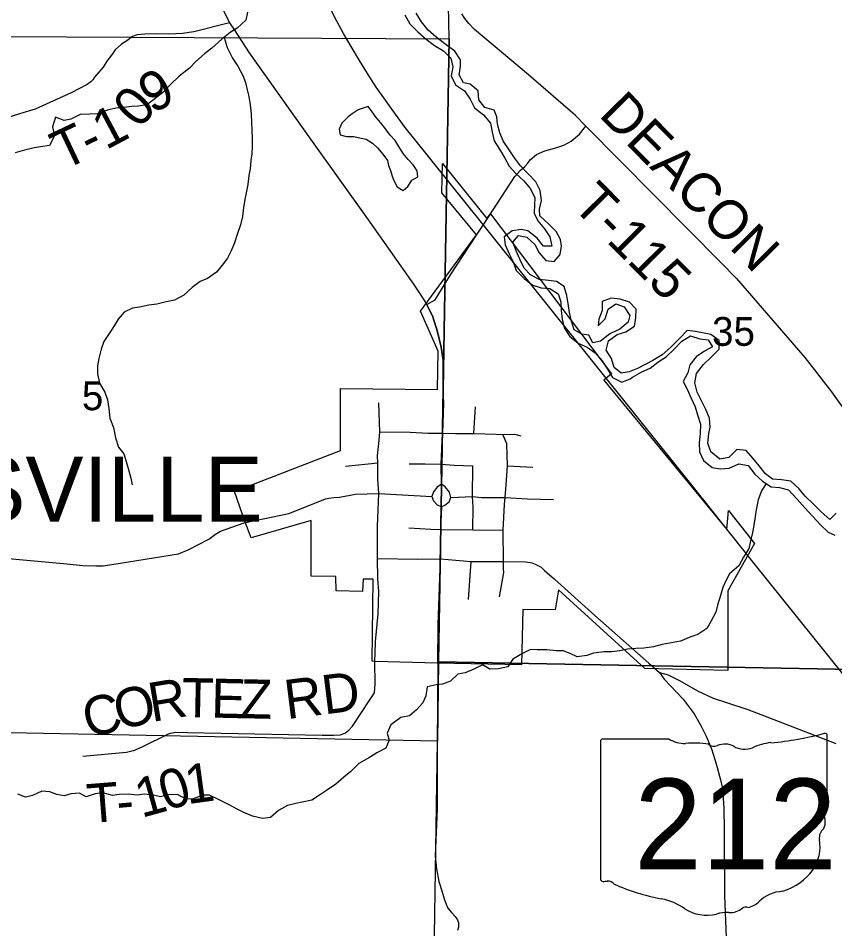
# Model space of a CAD drawing. Extents: x 0 to 34, y 0 to 22.
# Drawn here: x 3.131 to 4.318, y 18.627 to 19.951 of the extents above; entities that cross this region are included whole.
import ezdxf

# ---------------------------------------------------------------- set-up
doc = ezdxf.new("R2010")
doc.units = 0
for name, color, linetype in [('Default', 7, 'Continuous'), ('GM_X_City_Street', 7, 'Continuous'), ('GM_X_Corporation', 7, 'Continuous'), ('GM_X_County_Road', 7, 'Continuous'), ('GM_X_County_Road_Text', 7, 'Continuous'), ('GM_X_Interchange_Ramps', 7, 'Continuous'), ('GM_X_Interstate_Route', 7, 'Continuous'), ('GM_X_Major_River_Text', 7, 'Continuous'), ('GM_X_Minor_Lake', 7, 'Continuous'), ('GM_X_Minor_River', 7, 'Continuous'), ('GM_X_Section', 7, 'Continuous'), ('GM_X_Township_Road_Text', 7, 'Continuous'), ('GM_X_Township_Text', 7, 'Continuous'), ('GM_X_Unincorporated', 7, 'Continuous'), ('GM_X_Unincorporated_Text', 7, 'Continuous'), ('GM_X_US_Location', 7, 'Continuous')]:
    doc.layers.add(name, color=color, linetype=linetype)

msp = doc.modelspace()

# ---------------------------------------------------------------- linework, layer by layer
at = {"layer": 'Default'}
msp.add_lwpolyline([(3.7753, 20.9), (2.759, 20.9), (2.7373, 19.9264), (3.7574, 19.9211), (3.7556, 20.0185)], close=True, dxfattribs=at)
at = {"layer": 'GM_X_City_Street'}
msp.add_lwpolyline([(3.4457, 19.2626), (3.5997, 19.3223), (3.5997, 19.4123), (3.7404, 19.411), (3.7417, 19.467), (3.7161, 19.5247), (3.7972, 19.636), (3.747, 19.697), (3.748, 19.7395), (3.8125, 19.6595), (3.8178, 19.6664), (3.9934, 19.434), (3.9825, 19.4244), (4.1614, 19.2072), (4.1637, 19.2349), (4.2016, 19.1872), (4.1629, 19.1183), (4.1626, 19.0024), (4.0419, 19.0051), (3.9164, 19.1198), (3.9117, 19.0905), (3.8647, 19.0913), (3.8625, 19.0106), (3.7408, 19.0131), (3.6494, 19.0157), (3.6454, 19.0158), (3.6472, 19.1353), (3.6324, 19.1354), (3.6314, 19.1173), (3.5932, 19.1183), (3.5929, 19.1393), (3.557, 19.1395), (3.5569, 19.2207), (3.4695, 19.1951), (3.4612, 19.2182)], close=True, dxfattribs=at)
at = {"layer": 'GM_X_Corporation'}
for p, q in [((3.7458, 19.3025), (3.7478, 19.3473)), ((3.7463, 19.2732), (3.7458, 19.3025))]:
    msp.add_line(p, q, dxfattribs=at)
for points in [[(3.8079, 19.6516), (3.8532, 19.7209), (3.861, 19.7293), (3.8678, 19.7354), (3.8718, 19.7402), (3.8754, 19.7452), (3.8846, 19.7528), (3.8967, 19.7579), (3.9125, 19.7624), (3.9243, 19.7665), (3.9351, 19.7722), (3.9471, 19.7824), (3.9561, 19.7938), (3.9411, 19.8095), (3.8727, 19.8687), (3.7945, 19.9343), (3.786, 19.9433), (3.7801, 19.9505), (3.7759, 19.9571)], [(3.725, 19.5344), (3.7373, 19.5415), (3.7597, 19.5778), (3.7974, 19.6354), (3.8079, 19.6516)], [(3.749, 19.4004), (3.7489, 19.4537), (3.746, 19.4725), (3.7406, 19.4951), (3.734, 19.5166), (3.725, 19.5344)], [(3.7478, 19.3473), (3.7491, 19.3908), (3.749, 19.4004)], [(3.7602, 19.2542), (3.7581, 19.2615), (3.7518, 19.2694), (3.7463, 19.2732)], [(3.4595, 19.217), (3.4614, 19.2177), (3.5246, 19.2306), (3.5503, 19.2409), (3.578, 19.2521), (3.5826, 19.2532), (3.5901, 19.254), (3.5981, 19.2543), (3.6212, 19.2588), (3.6555, 19.2597), (3.7325, 19.2556)], [(3.7325, 19.2556), (3.7349, 19.2492), (3.7401, 19.2435), (3.7464, 19.2402)], [(3.7464, 19.2402), (3.7515, 19.2427), (3.7577, 19.2475), (3.7602, 19.2542)], [(2.1, 18.8956), (2.109, 18.8968), (2.1275, 18.9017), (2.1814, 18.9185), (2.2418, 18.9368), (2.293, 18.9513), (2.3675, 18.9688), (2.6484, 19.0502), (3.0219, 19.1608), (3.0376, 19.1648), (3.0493, 19.1666), (3.0647, 19.1685), (3.0897, 19.1679), (3.1971, 19.1578), (3.225, 19.1553), (3.244, 19.1548), (3.2547, 19.1546), (3.2795, 19.1586), (3.364, 19.1721), (3.3779, 19.1781), (3.4083, 19.1935), (3.4181, 19.2006), (3.4252, 19.2052), (3.4595, 19.217)]]:
    msp.add_lwpolyline(points, dxfattribs=at)
at = {"layer": 'GM_X_County_Road'}
msp.add_lwpolyline([(4.3317, 18.995), (4.1992, 19.1604), (4.1109, 19.2714), (3.8063, 19.6512), (3.7056, 19.7772), (3.6936, 19.7922), (3.6834, 19.8062), (3.6732, 19.8199), (3.6625, 19.8349), (3.6516, 19.8508), (3.6386, 19.8706), (3.627, 19.8892), (3.6149, 19.9097), (3.604, 19.9289), (3.5943, 19.9464), (3.584, 19.9663)], dxfattribs=at)
at = {"layer": 'GM_X_Interchange_Ramps'}
for p, q in [((3.7143, 19.5509), (3.725, 19.5344)), ((3.7478, 19.3473), (3.7458, 19.3025)), ((3.7458, 19.3025), (3.7463, 19.2732)), ((4.0477, 19.013), (4.0632, 18.9994))]:
    msp.add_line(p, q, dxfattribs=at)
for points in [[(3.4051, 20.0126), (3.4382, 19.944), (3.4453, 19.9335), (3.4666, 19.9005), (3.5559, 19.7752), (3.6386, 19.659), (3.7057, 19.5641), (3.7143, 19.5509)], [(3.725, 19.5344), (3.734, 19.5166), (3.7406, 19.4951), (3.746, 19.4725), (3.7489, 19.4537), (3.749, 19.4004)], [(3.749, 19.4004), (3.7491, 19.3908), (3.7478, 19.3473)], [(3.7463, 19.2732), (3.7403, 19.2692), (3.7346, 19.2624), (3.7325, 19.2556)], [(3.7602, 19.2542), (3.7581, 19.2615), (3.7518, 19.2694), (3.7463, 19.2732)], [(3.7325, 19.2556), (3.7349, 19.2492), (3.7401, 19.2435), (3.7464, 19.2402)], [(3.7464, 19.2402), (3.7515, 19.2427), (3.7577, 19.2475), (3.7602, 19.2542)], [(3.7464, 19.2402), (3.745, 19.2075), (3.7451, 19.1649), (3.7896, 19.161), (3.8365, 19.1607), (3.869, 19.1602), (3.8781, 19.1588), (3.8843, 19.156), (3.8911, 19.1525), (3.8962, 19.1478), (3.91, 19.1357)], [(3.91, 19.1357), (3.9108, 19.135), (3.9692, 19.0823), (4.0477, 19.013)], [(4.0632, 18.9994), (4.076, 18.9962), (4.0924, 18.9878), (4.1186, 18.9728), (4.1414, 18.962), (4.1609, 18.9557), (4.1918, 18.9455), (4.2423, 18.9265), (4.3195, 18.8965)], [(4.0632, 18.9994), (4.0702, 18.99), (4.0978, 18.9605), (4.1137, 18.9395), (4.1239, 18.9217), (4.1319, 18.9059), (4.1394, 18.887), (4.1458, 18.8667), (4.1522, 18.8436), (4.1547, 18.8306), (4.157, 18.8022), (4.1573, 18.7698), (4.1576, 18.6754), (4.1601, 18.6141)]]:
    msp.add_lwpolyline(points, dxfattribs=at)
at = {"layer": 'GM_X_Interstate_Route'}
for points in [[(3.4382, 19.944), (3.3865, 19.9309), (3.3697, 19.9286), (3.3604, 19.9281)], [(3.3604, 19.9281), (3.3502, 19.9276), (3.3323, 19.9283), (3.3151, 19.9279), (3.3042, 19.9269), (3.297, 19.9243), (3.2891, 19.918), (3.281, 19.913), (3.2718, 19.905), (3.2666, 19.8972), (3.26, 19.8886), (3.2544, 19.8797), (3.242, 19.8652), (3.2396, 19.8613), (3.2368, 19.8584), (3.2313, 19.8544), (3.2081, 19.8424), (3.1556, 19.8186), (3.1329, 19.8121), (3.1129, 19.8056), (3.1016, 19.7988), (3.0978, 19.7973), (3.0767, 19.7884), (2.9777, 19.7218)], [(3.9561, 19.7938), (4.1532, 19.5954), (4.1751, 19.5722), (4.2745, 19.4577), (4.3136, 19.4078), (4.329, 19.3859)], [(3.2248, 18.8779), (3.2883, 18.8839), (3.2963, 18.8854), (3.299, 18.886), (3.3114, 18.8915), (3.3496, 18.9105), (3.3523, 18.9112), (3.3555, 18.912), (3.3591, 18.9125), (3.3774, 18.9121), (3.573, 18.9082), (3.5895, 18.9085), (3.5998, 18.909), (3.6068, 18.9119), (3.6117, 18.9157), (3.6168, 18.9214), (3.6421, 18.9597), (3.6488, 18.9698), (3.65, 18.9828), (3.6496, 19.0151)], [(3.741, 19.0125), (3.7399, 18.8937), (3.74, 18.8011), (3.7371, 18.7324), (3.739, 18.7142), (3.7427, 18.6955), (3.7469, 18.6818), (3.7503, 18.6703), (3.7531, 18.6626), (3.7557, 18.6568), (3.7611, 18.6507), (3.7665, 18.6445), (3.7695, 18.64), (3.7711, 18.6353), (3.7713, 18.6294), (3.7695, 18.6241)]]:
    msp.add_lwpolyline(points, dxfattribs=at)
at = {"layer": 'GM_X_Minor_Lake'}
for points in [[(3.7556, 20.0185), (4.6053, 19.9945), (4.5812, 18.9996), (3.7421, 19.0151), (3.7574, 19.9211)], [(2.7373, 19.9264), (3.7574, 19.9211), (3.7421, 19.0151), (3.7408, 18.8998), (2.719, 18.9194)], [(3.7421, 19.0151), (4.5812, 18.9996), (4.5642, 17.9795), (3.7264, 17.9888), (3.7408, 18.8998)]]:
    msp.add_lwpolyline(points, close=True, dxfattribs=at)
at = {"layer": 'GM_X_Minor_River'}
for points in [[(3.6397, 19.8223), (3.6253, 19.8176), (3.6167, 19.8119), (3.6106, 19.8077), (3.6016, 19.7985), (3.5975, 19.7897), (3.5991, 19.7814), (3.6082, 19.7788), (3.6192, 19.7789), (3.6295, 19.7767), (3.6371, 19.7752), (3.6459, 19.7693), (3.6536, 19.7625), (3.6612, 19.7534), (3.6678, 19.744), (3.6694, 19.7368), (3.6721, 19.7296), (3.6748, 19.7213), (3.6771, 19.7149), (3.6818, 19.7058), (3.6906, 19.7006), (3.6973, 19.7063), (3.7019, 19.7132)], [(3.7019, 19.7132), (3.7033, 19.7155), (3.712, 19.7201), (3.7112, 19.7292), (3.7054, 19.7375), (3.6978, 19.7454), (3.6905, 19.7541), (3.6843, 19.7643), (3.6793, 19.773), (3.6716, 19.7809), (3.6651, 19.7899), (3.6582, 19.7986), (3.6516, 19.8065), (3.6455, 19.8148), (3.6397, 19.8223)]]:
    msp.add_lwpolyline(points, dxfattribs=at)
at = {"layer": 'GM_X_Township_Road_Text'}
for points in [[(3.4642, 19.9597), (3.462, 19.9483), (3.4496, 19.9364), (3.439, 19.9299), (3.4273, 19.9203), (3.4126, 19.9076), (3.402, 19.8992), (3.3892, 19.8881), (3.3802, 19.8781), (3.3651, 19.8666), (3.3523, 19.8544), (3.3414, 19.8429), (3.3278, 19.8322), (3.318, 19.8249), (3.3059, 19.8229), (3.296, 19.8224), (3.285, 19.8212), (3.2732, 19.8203), (3.2607, 19.8172), (3.2459, 19.8121), (3.2346, 19.8116), (3.2213, 19.8111), (3.2077, 19.8042), (3.1978, 19.8022), (3.1852, 19.807), (3.1808, 19.793), (3.1836, 19.7801), (3.1765, 19.7656), (3.1636, 19.764), (3.1541, 19.7624), (3.1401, 19.7592), (3.1264, 19.7553)], [(3.4306, 19.923), (3.435, 19.9082), (3.4424, 19.8927), (3.4504, 19.881), (3.4574, 19.8678), (3.4613, 19.8576), (3.464, 19.847), (3.4664, 19.8371), (3.4684, 19.825), (3.4697, 19.8118), (3.4702, 19.7992), (3.4706, 19.7875), (3.4711, 19.7765), (3.4712, 19.7643), (3.4709, 19.7537), (3.4691, 19.7438), (3.4681, 19.7317), (3.4663, 19.7222), (3.4649, 19.7093), (3.4627, 19.6994), (3.4609, 19.6895), (3.4587, 19.6758), (3.4573, 19.6625), (3.454, 19.6507), (3.4492, 19.6363), (3.4455, 19.6241), (3.4403, 19.6115), (3.4354, 19.602), (3.4275, 19.5917), (3.4193, 19.5818), (3.4061, 19.5722), (3.3955, 19.5679), (3.3838, 19.5591), (3.3717, 19.548), (3.3581, 19.541), (3.3444, 19.5379), (3.3327, 19.5351), (3.3209, 19.5335), (3.3073, 19.5307), (3.2974, 19.5295), (3.2849, 19.5237), (3.2763, 19.5134), (3.2707, 19.5038), (3.2643, 19.4939), (3.2557, 19.4806), (3.2516, 19.4695), (3.2483, 19.4562), (3.2465, 19.4452), (3.2462, 19.4342), (3.2494, 19.4202), (3.2571, 19.407), (3.261, 19.396), (3.263, 19.3835), (3.2642, 19.3695), (3.2697, 19.3558), (3.2725, 19.3407), (3.2768, 19.3274), (3.2844, 19.3176), (3.288, 19.3063), (3.2919, 19.2927), (3.295, 19.2821), (3.2966, 19.2726)], [(4.2182, 19.2743), (4.2117, 19.2637), (4.2068, 19.2507), (4.2039, 19.2359), (4.2025, 19.2264), (4.2003, 19.2135), (4.1985, 19.2032), (4.1959, 19.1929), (4.193, 19.18), (4.1855, 19.1674), (4.1788, 19.1545), (4.1652, 19.143), (4.1596, 19.133), (4.1555, 19.1231), (4.1522, 19.1114), (4.1478, 19.0973), (4.1452, 19.087), (4.1381, 19.0737), (4.1321, 19.0634), (4.1189, 19.0549), (4.109, 19.0514), (4.0939, 19.0452), (4.0833, 19.0432), (4.0674, 19.0404), (4.0545, 19.0369), (4.0404, 19.0349), (4.0287, 19.0344), (4.0169, 19.0332), (4.0055, 19.0312), (3.9938, 19.0295), (3.9828, 19.0295), (3.9676, 19.0278), (3.9577, 19.0243), (3.9437, 19.0223), (3.9334, 19.0271), (3.9235, 19.0312), (3.9132, 19.0308), (3.8995, 19.0325), (3.8855, 19.0324), (3.876, 19.0331), (3.8643, 19.0269), (3.8503, 19.0188), (3.8428, 19.0078), (3.8291, 19.005), (3.8166, 19.0045), (3.8059, 19.0105), (3.7934, 19.0043), (3.781, 18.9989), (3.77, 18.9969), (3.7594, 18.9869), (3.7481, 18.9823), (3.7386, 18.9815), (3.7257, 18.9787), (3.7235, 18.9658), (3.7194, 18.9555), (3.71, 18.9452), (3.6998, 18.9363), (3.6873, 18.9343), (3.673, 18.9236), (3.6674, 18.9114), (3.6705, 18.9012), (3.6653, 18.8897), (3.6524, 18.8828), (3.6419, 18.8759), (3.6264, 18.8674), (3.6147, 18.8555), (3.6045, 18.8475), (3.5928, 18.8371), (3.5792, 18.8279), (3.569, 18.8213), (3.5577, 18.8137), (3.544, 18.8109), (3.5346, 18.8089), (3.5224, 18.8061), (3.5096, 18.7988), (3.4979, 18.7885), (3.4861, 18.7872), (3.4717, 18.7905), (3.4591, 18.7957), (3.4495, 18.801), (3.4389, 18.8066), (3.4232, 18.8144), (3.4091, 18.8211), (3.3996, 18.821), (3.3852, 18.8156), (3.3754, 18.8155), (3.3624, 18.8219), (3.3495, 18.8214), (3.3381, 18.8186), (3.3275, 18.8212), (3.3141, 18.8226), (3.3039, 18.821), (3.2914, 18.8224), (3.2777, 18.8219), (3.2682, 18.8207), (3.2541, 18.8243), (3.2431, 18.8231), (3.2299, 18.8188), (3.2203, 18.8241), (3.2078, 18.8232), (3.1979, 18.8201)], [(3.1979, 18.8201), (3.1873, 18.8223), (3.177, 18.826), (3.1652, 18.827), (3.1516, 18.8208), (3.1417, 18.8184), (3.1303, 18.8225)]]:
    msp.add_lwpolyline(points, dxfattribs=at)
at = {"layer": 'GM_X_Unincorporated'}
for p, q in [((3.7935, 19.3471), (3.7958, 19.386)), ((3.607, 19.2994), (3.6538, 19.3044)), ((3.8422, 19.2999), (3.8794, 19.298)), ((3.7859, 19.1055), (3.7896, 19.161))]:
    msp.add_line(p, q, dxfattribs=at)
for points in [[(3.6556, 19.3371), (3.6568, 19.3494), (3.6554, 19.3916)], [(3.6568, 19.3494), (3.701, 19.3491), (3.7268, 19.3474), (3.7478, 19.3473), (3.7669, 19.3469), (3.7935, 19.3471), (3.826, 19.3463), (3.8358, 19.3455), (3.8524, 19.3463), (3.8616, 19.3438)], [(3.8367, 19.1501), (3.8365, 19.1607), (3.8362, 19.2065), (3.838, 19.2438), (3.8391, 19.2541), (3.8405, 19.2724), (3.8422, 19.2999), (3.8413, 19.3321), (3.8358, 19.3455)], [(3.6507, 19.0448), (3.6543, 19.0846), (3.6551, 19.1174), (3.6539, 19.1356), (3.6536, 19.1653), (3.6536, 19.2116), (3.6555, 19.2597), (3.6541, 19.2807), (3.6538, 19.3044), (3.6535, 19.3149), (3.6556, 19.3371)], [(3.6995, 19.303), (3.7228, 19.3028), (3.7458, 19.3025), (3.7648, 19.301), (3.7922, 19.2999)], [(3.7921, 19.207), (3.7923, 19.24), (3.7915, 19.2552), (3.7922, 19.2999)], [(3.7602, 19.2542), (3.7915, 19.2552), (3.8044, 19.2541), (3.8391, 19.2541), (3.8716, 19.2521), (3.9094, 19.2513)], [(3.6987, 19.21), (3.7311, 19.2081), (3.745, 19.2075), (3.7921, 19.207), (3.8362, 19.2065)], [(3.6536, 19.1653), (3.7118, 19.1644), (3.7451, 19.1649)], [(3.741, 19.0125), (3.7418, 19.07), (3.7451, 19.1649)], [(3.8308, 19.1093), (3.8368, 19.1448), (3.8367, 19.1501)], [(3.6496, 19.0151), (3.6505, 19.0433), (3.6507, 19.0448)]]:
    msp.add_lwpolyline(points, dxfattribs=at)
at = {"layer": 'GM_X_Unincorporated_Text'}
for p, q in [((3.9777, 18.8994), (3.9777, 18.6992)), ((4.0774, 18.9028), (3.9809, 18.9028)), ((4.3072, 18.8031), (4.3072, 18.9078)), ((4.3072, 18.8031), (4.3072, 18.8031))]:
    msp.add_line(p, q, dxfattribs=at)
for centre, major_axis, start_param, end_param in [((4.1898, 19.1756), (0.3495, 0), 4.814394, 5.042369), ((4.3036, 18.9082), (0.00367, 0), 6.141152, 7.989035), ((3.9814, 18.8998), (0.00382, 0), 1.712693, 3.28349), ((4.1004, 18.926), (0.037, 0), 4.042523, 4.731795), ((4.1127, 18.7905), (0.133, 0), 1.404758, 1.657858), ((4.1429, 18.9008), (0.0107, 0), 3.836095, 5.185415), ((4.1586, 18.8777), (0.0222, 0), 0.950623, 2.079405), ((4.2344, 18.8417), (0.0703, 0), 1.699011, 2.107814), ((4.1872, 18.9094), (0.0267, 0), 4.081561, 5.145723), ((4.3033, 18.8027), (0.00393, 0), 5.05454, 6.418171), ((4.3064, 18.7954), (0.00568, 0), 1.883978, 3.671073), ((4.2703, 18.7822), (0.0341, 0), 5.934695, 6.695948), ((4.3204, 18.7593), (0.0248, 0), 2.387724, 3.262537), ((4.2094, 18.746), (0.0874, 0), 5.101752, 6.440018), ((3.9815, 18.6988), (0.00385, 0), 3.00124, 4.508301), ((3.9821, 18.7193), (0.0294, 0), 4.665946, 4.897461), ((3.9881, 18.6877), (0.0106, 0), 0.519207, 1.627899), ((4.1219, 18.8675), (0.2524, 0), 4.195997, 4.488961), ((4.0466, 18.6093), (0.079, 0), 0.823519, 1.323587), ((4.2463, 18.6431), (0.0479, 0), 1.647645, 2.488434), ((4.1647, 18.6717), (0.0267, 0), 4.691044, 5.507374), ((4.1888, 18.6523), (0.00752, 0), 1.147584, 2.315152), ((4.1856, 18.6799), (0.0282, 0), 4.937069, 5.64225), ((4.1321, 18.6867), (0.0501, 0), 4.026481, 4.996735), ((4.161, 18.6175), (0.0412, 0), 1.495662, 1.94098)]:
    msp.add_ellipse(centre, major_axis=major_axis, ratio=0.8, start_param=start_param, end_param=end_param, dxfattribs=at)
at = {"layer": 'GM_X_US_Location'}
for points in [[(3.6931, 19.956), (3.7005, 19.9429), (3.7121, 19.9309), (3.7241, 19.9205), (3.736, 19.9112), (3.7491, 19.9035), (3.7599, 19.893), (3.7628, 19.8802), (3.7607, 19.8669), (3.767, 19.8541), (3.7797, 19.8452), (3.7883, 19.8332), (3.7946, 19.8208), (3.8077, 19.8104), (3.8177, 19.7984), (3.8199, 19.7851), (3.8231, 19.7727), (3.8305, 19.7603), (3.8384, 19.7475), (3.845, 19.7358), (3.8547, 19.725), (3.8663, 19.7146), (3.8756, 19.7026), (3.8823, 19.6898), (3.8817, 19.6799), (3.8811, 19.6674), (3.8866, 19.6561), (3.896, 19.6445), (3.9038, 19.6329), (3.907, 19.6193), (3.8949, 19.6194), (3.8855, 19.631), (3.8717, 19.6418), (3.8621, 19.6436), (3.8492, 19.6418), (3.8376, 19.6329), (3.8389, 19.6212), (3.8449, 19.6084), (3.8504, 19.5967), (3.8551, 19.5839), (3.8667, 19.5723), (3.8794, 19.5626), (3.8913, 19.559), (3.9039, 19.5581), (3.9161, 19.55), (3.9201, 19.5387), (3.9203, 19.5261), (3.9217, 19.5133), (3.9249, 19.5008), (3.9331, 19.488), (3.9451, 19.4784), (3.9581, 19.4725), (3.97, 19.4643), (3.9793, 19.4531), (3.9879, 19.4404), (3.995, 19.4283), (4.0084, 19.4217), (4.0208, 19.4265)], [(3.8758, 19.5778), (3.8665, 19.5875), (3.8602, 19.6003), (3.855, 19.6127), (3.8499, 19.6255), (3.8585, 19.6351), (3.8703, 19.6327), (3.8819, 19.6219), (3.8882, 19.6098), (3.8982, 19.5986), (3.9104, 19.5973), (3.919, 19.6073), (3.9211, 19.6195), (3.9194, 19.6293), (3.9131, 19.6406), (3.9023, 19.6514), (3.8896, 19.6637), (3.889, 19.6732), (3.8918, 19.6858), (3.8897, 19.7002), (3.8834, 19.713), (3.8722, 19.7245), (3.8614, 19.7361), (3.8524, 19.7481), (3.8446, 19.7597), (3.8364, 19.7718), (3.8313, 19.7842), (3.828, 19.797), (3.8267, 19.8073), (3.8228, 19.8171), (3.8094, 19.821), (3.8008, 19.8322), (3.7995, 19.8455), (3.7879, 19.8552), (3.7784, 19.8569), (3.7721, 19.8686), (3.7742, 19.8807), (3.774, 19.8906), (3.7658, 19.903), (3.7531, 19.9123), (3.7389, 19.9234), (3.7269, 19.9335), (3.7172, 19.9458), (3.7094, 19.9582)], [(3.9886, 19.4901), (3.9777, 19.4812), (3.9664, 19.4787), (3.9605, 19.49), (3.9506, 19.4913), (3.9394, 19.498), (3.9354, 19.5104), (3.9326, 19.5229), (3.9308, 19.5362), (3.9287, 19.5479), (3.9247, 19.5607), (3.9136, 19.5681), (3.9018, 19.5695), (3.8884, 19.5708), (3.8758, 19.5778)], [(4.3202, 19.2314), (4.3112, 19.2218), (4.2985, 19.233), (4.2869, 19.2449), (4.2753, 19.2557), (4.2664, 19.2666), (4.2544, 19.2778), (4.2407, 19.2798), (4.2277, 19.2808), (4.2174, 19.2882), (4.2084, 19.3002), (4.1991, 19.3114), (4.1894, 19.3223), (4.1757, 19.3239), (4.1641, 19.3123), (4.1512, 19.3099), (4.1378, 19.3206), (4.1338, 19.3331), (4.135, 19.3468), (4.1368, 19.3563), (4.1362, 19.3692), (4.1307, 19.382), (4.1244, 19.3944), (4.1181, 19.4072), (4.1148, 19.4208), (4.1172, 19.4345), (4.1273, 19.4476), (4.1385, 19.458), (4.1501, 19.4696), (4.1503, 19.4825), (4.138, 19.491), (4.1284, 19.4931), (4.1155, 19.4952), (4.1037, 19.4969), (4.0925, 19.4853), (4.0797, 19.4726), (4.067, 19.4614), (4.0535, 19.4532), (4.0437, 19.4477), (4.0312, 19.4414), (4.0191, 19.4367), (4.0074, 19.435), (3.9974, 19.4432), (3.9934, 19.456), (3.9856, 19.468), (3.9891, 19.4817), (4.0019, 19.4911), (4.0144, 19.4951), (4.0272, 19.5029), (4.0289, 19.5154), (4.0294, 19.5276), (4.0197, 19.538), (4.006, 19.5423), (3.993, 19.5437), (3.9802, 19.5389), (3.98, 19.526), (3.9753, 19.5134), (3.9743, 19.5035), (3.9844, 19.5139), (3.9887, 19.5276), (4, 19.5354), (4.0119, 19.5314), (4.0204, 19.5187), (4.0176, 19.5091), (4.0056, 19.4987), (3.992, 19.4924), (3.9886, 19.4901)], [(4.0208, 19.4265), (4.0242, 19.4288), (4.0378, 19.4366), (4.0498, 19.4418), (4.0607, 19.4507), (4.0731, 19.4585), (4.0847, 19.4697), (4.0959, 19.4812), (4.1084, 19.489), (4.1221, 19.4847), (4.1343, 19.4834), (4.1405, 19.4732), (4.1289, 19.467), (4.1165, 19.4584), (4.1075, 19.4469), (4.1043, 19.4351), (4.0977, 19.4228), (4.1036, 19.4115), (4.1087, 19.3995), (4.115, 19.3859), (4.1186, 19.3742), (4.123, 19.3606), (4.1225, 19.347), (4.1208, 19.3333), (4.1214, 19.3204), (4.1273, 19.3079), (4.14, 19.2975), (4.1522, 19.2958), (4.1648, 19.2968), (4.1787, 19.3027), (4.1924, 19.3007), (4.2018, 19.2879), (4.213, 19.2775), (4.2256, 19.2697), (4.2378, 19.2684), (4.2508, 19.2652), (4.2632, 19.2521), (4.2744, 19.239), (4.2864, 19.2263), (4.2973, 19.2144), (4.3085, 19.2035), (4.3184, 19.1992)]]:
    msp.add_lwpolyline(points, dxfattribs=at)

# ---------------------------------------------------------------- texts
at = {"layer": 'GM_X_County_Road_Text'}
for s, height, p in [('35', 0.04186, (4.1398, 19.4745)), ('5', 0.0419, (3.2236, 19.3809))]:
    msp.add_text(s, height=height, rotation=0, dxfattribs=at).set_placement(p)
at = {"layer": 'GM_X_Major_River_Text'}
msp.add_text('LEESVILLE', height=0.0947, rotation=0, dxfattribs=at).set_placement((2.8177, 19.2187))
at = {"layer": 'GM_X_Section'}
for s, height, rotation, p in [('9', 0.0568, 27.9034, (3.3257, 19.8113)), ('0', 0.0568, 48.1531, (3.3065, 19.7885)), ('DEACON', 0.05682, 314.6496, (3.9736, 19.8093)), ('1', 0.0568, 28.0076, (3.2586, 19.7587)), ('T', 0.0568, 25.4083, (3.1966, 19.7291)), ('-', 0.0568, 25.6389, (3.2352, 19.7474)), ('T-115', 0.05682, 314.8019, (3.9344, 19.6774)), ('R', 0.0568, 9.461, (3.3253, 18.9274)), ('T', 0.0568, 358.9093, (3.3686, 18.9349)), ('E', 0.0568, 358.6842, (3.411, 18.934)), ('Z', 0.0568, 358.6842, (3.4535, 18.9331)), ('RD', 0.05682, 7.1885, (3.5216, 18.9316)), ('O', 0.0568, 14.4038, (3.2782, 18.9152)), ('C', 0.0568, 14.4187, (3.233, 18.9036)), ('0', 0.0568, 17.8064, (3.3463, 18.7979)), ('1', 0.0568, 7.7912, (3.3771, 18.808)), ('1', 0.0568, 15.4492, (3.3102, 18.7879)), ('T', 0.0568, 4.5711, (3.233, 18.7803)), ('-', 0.0568, 5.222, (3.2761, 18.7837))]:
    msp.add_text(s, height=height, rotation=rotation, dxfattribs=at).set_placement(p)
at = {"layer": 'GM_X_Township_Text'}
for s in ['s', 'r']:
    msp.add_text(s, height=0.000189, dxfattribs=at).set_placement((4.1387, 18.786))
msp.add_text('212', height=0.000189, rotation=0, dxfattribs=at).set_placement((4.0719, 18.7722))
at = {"layer": 'GM_X_Unincorporated_Text'}
msp.add_text('212', height=0.13184, dxfattribs=at).set_placement((4.0267, 18.7134))

doc.saveas('drawing.dxf')
